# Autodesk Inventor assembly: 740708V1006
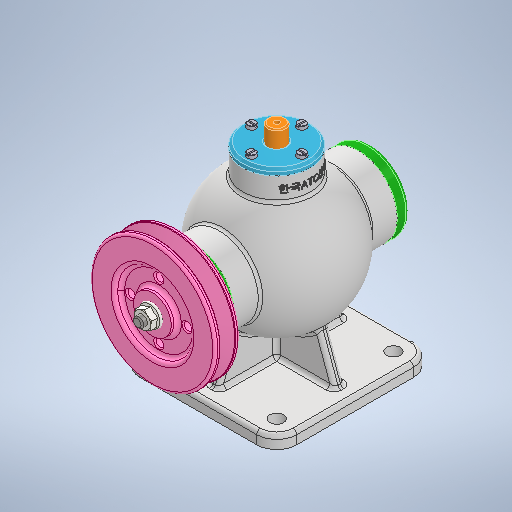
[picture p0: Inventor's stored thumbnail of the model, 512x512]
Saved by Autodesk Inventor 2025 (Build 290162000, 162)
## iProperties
Created: 2024-07
Part Number: 740708V1006
Document SubType Name: Assembly
Designer: parkm
Author: parkm
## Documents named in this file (15)
- C:\Users\parkm\OneDrive\바탕 화면\740708V1006\740708V1006.iam
- C:\Users\parkm\OneDrive\바탕 화면\740708V1006\본체.ipt
- C:\Users\parkm\OneDrive\바탕 화면\740708V1006\뒤커버\뒤커버.ipt
- C:\Users\parkm\OneDrive\바탕 화면\740708V1006\베어링- 6202\베어링- 6202.ipt
- C:\Users\parkm\OneDrive\바탕 화면\740708V1006\편심축\편심축.ipt
- C:\Users\parkm\OneDrive\바탕 화면\740708V1006\칼라\칼라.ipt
- C:\Users\parkm\OneDrive\바탕 화면\740708V1006\앞커버\앞커버.ipt
- C:\Users\parkm\OneDrive\바탕 화면\740708V1006\오일실 15 30 7\오일실 15 30 7.ipt
- C:\Users\parkm\OneDrive\바탕 화면\740708V1006\볼트 M4 x 16\볼트 M4 x 16.ipt
- C:\Users\parkm\OneDrive\바탕 화면\740708V1006\키 4 x 4 x 12\키 4 x 4 x 12.ipt
- C:\Users\parkm\OneDrive\바탕 화면\740708V1006\V-벨트풀리\V-벨트풀리.ipt
- C:\Users\parkm\OneDrive\바탕 화면\740708V1006\너트 M8\너트 M8.ipt
- C:\Users\parkm\OneDrive\바탕 화면\740708V1006\슬라이드\슬라이드.ipt
- C:\Users\parkm\OneDrive\바탕 화면\740708V1006\상부커버\상부커버.ipt
- C:\Users\parkm\OneDrive\바탕 화면\740708V1006\볼트 M4 x 12\볼트 M4 x 12.ipt
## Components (1 placed, 1 different names)
1. V-벨트풀리:1
